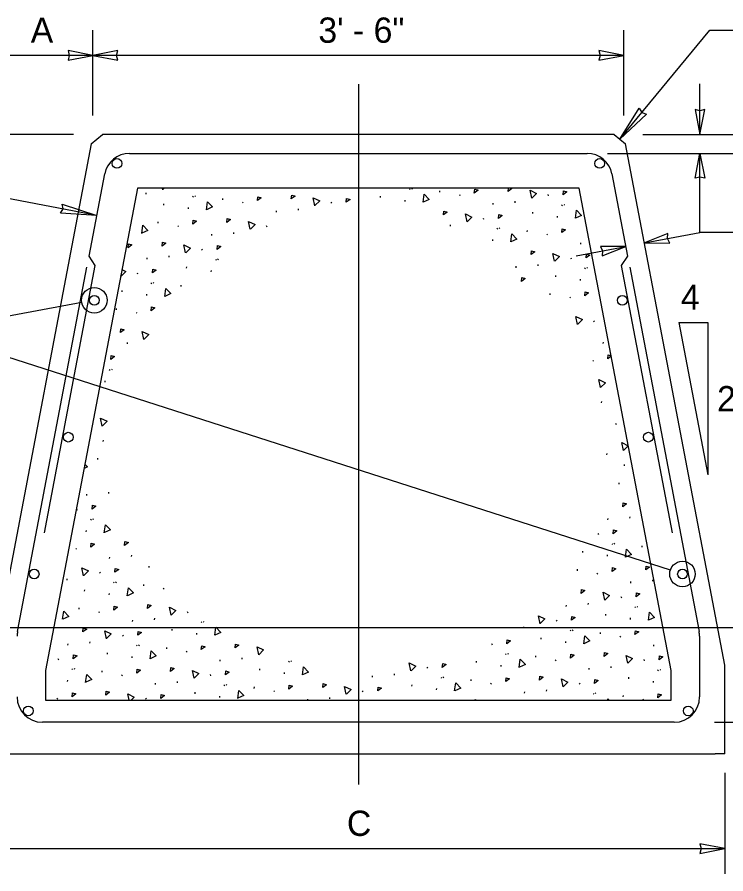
# Model space of a CAD drawing. Extents: x 99862 to 103151, y 100000 to 102076.
# Drawn here: x 100955 to 101404, y 100434 to 100977 of the extents above; entities that cross this region are included whole.
import ezdxf

# ---------------------------------------------------------------- set-up
doc = ezdxf.new("R2010")
doc.units = 0
for name, color, linetype in [('Level 10', 7, 'Continuous'), ('Level 13', 7, 'Continuous'), ('Level 15', 7, 'Continuous'), ('Level 2', 7, 'Continuous'), ('Level 20', 7, 'Continuous'), ('Level 8', 7, 'Continuous')]:
    doc.layers.add(name, color=color, linetype=linetype)

msp = doc.modelspace()

# ---------------------------------------------------------------- linework, layer by layer
at = {"layer": 'Level 10'}
for p, q in [((101026.08, 100890.26), (101315.75, 100890.26)), ((101000.45, 100825.21), (101010.36, 100877.26)), ((101331.47, 100877.26), (101341.38, 100825.21)), ((101004.42, 100819.36), (101000.45, 100825.21)), ((101341.38, 100825.21), (101337.41, 100819.36)), ((100955.2, 100587.61), (100999.13, 100818.26)), ((100972.18, 100650.08), (101004.42, 100819.36)), ((101337.41, 100819.36), (101369.65, 100650.08)), ((101342.71, 100818.26), (101386.64, 100587.63)), ((101386.92, 100584.64), (101386.92, 100546.26)), ((101370.92, 100530.26), (100970.91, 100530.26))]:
    msp.add_line(p, q, dxfattribs=at)
for centre in [(101018.1, 100883.91), (101323.73, 100883.91), (101003.79, 100797.29), (101338.05, 100797.29), (100987.29, 100710.67), (101354.55, 100710.67), (100965.7, 100624.05), (101376.13, 100624.05), (100962.07, 100537.43), (101379.76, 100537.43)]:
    msp.add_circle(centre, 3.08, dxfattribs=at)
for centre, start, end in [((101026.08, 100874.26), 90, 169.216), ((101315.75, 100874.26), 10.784, 90), ((100970.91, 100584.62), 169.2152, 180), ((101370.92, 100584.64), 360, 10.784), ((100970.91, 100546.26), 180, 270), ((101370.92, 100546.26), 270, 360)]:
    msp.add_arc(centre, 16, start, end, dxfattribs=at)
at = {"layer": 'Level 13'}
for p, q in [((101031.05, 100868.26), (100972.91, 100563.05)), ((101310.79, 100868.26), (101031.05, 100868.26)), ((101036.59, 100864.44), (101036.65, 100865.31)), ((101159.93, 100868), (101159.94, 100868.26)), ((101203.25, 100867.87), (101203.77, 100867.49)), ((101204.6, 100868.14), (101205.11, 100867.76)), ((101222.42, 100865.66), (101222.48, 100866.54)), ((101234.79, 100864.12), (101235.31, 100863.74)), ((101290.81, 100864.18), (101291.17, 100863.46)), ((101368.92, 100563.07), (101310.79, 100868.26)), ((101047.71, 100857.52), (101047.77, 100858.4)), ((101065.99, 100863.11), (101066.51, 100862.74)), ((101067.33, 100863.39), (101067.85, 100863.01)), ((101085.15, 100860.91), (101085.21, 100861.78)), ((101097.53, 100859.37), (101098.04, 100858.99)), ((101153.55, 100859.43), (101153.9, 100858.71)), ((101184.97, 100862.28), (101185.03, 100863.15)), ((101200.58, 100859.89), (101200.64, 100860.76)), ((101256.28, 100857.86), (101256.34, 100858.73)), ((101270.21, 100859.05), (101270.27, 100859.93)), ((101063.32, 100855.14), (101063.38, 100856.01)), ((101119.01, 100853.11), (101119.07, 100853.98)), ((101132.94, 100854.3), (101133, 100855.17)), ((101281.32, 100852.14), (101281.39, 100853.01)), ((101299.61, 100857.73), (101300.12, 100857.35)), ((101300.95, 100858), (101301.47, 100857.62)), ((101249.9, 100849.29), (101250.26, 100848.57)), ((101296.94, 100849.75), (101297, 100850.62)), ((101044.24, 100846.02), (101044.3, 100846.89)), ((101056.61, 100844.48), (101057.13, 100844.1)), ((101112.63, 100844.54), (101112.99, 100843.82)), ((101229.3, 100844.16), (101229.36, 100845.04)), ((101258.7, 100842.84), (101259.21, 100842.46)), ((101260.04, 100843.11), (101260.56, 100842.73)), ((101078.1, 100838.22), (101078.16, 100839.09)), ((101092.03, 100839.41), (101092.09, 100840.28)), ((101277.86, 100840.63), (101277.92, 100841.51)), ((101290.23, 100839.09), (101290.75, 100838.71)), ((101256.02, 100834.86), (101256.08, 100835.73)), ((101311.72, 100832.83), (101311.78, 100833.7)), ((101071.72, 100829.65), (101072.08, 100828.93)), ((101037.19, 100823.33), (101037.25, 100824.2)), ((101051.12, 100824.52), (101051.18, 100825.39)), ((101080.52, 100823.2), (101081.04, 100822.82)), ((101081.86, 100823.47), (101082.38, 100823.09)), ((101305.34, 100824.26), (101305.7, 100823.54)), ((101062.24, 100817.6), (101062.3, 100818.48)), ((101077.85, 100815.22), (101077.91, 100816.09)), ((101270.81, 100817.94), (101270.87, 100818.81)), ((101284.74, 100819.13), (101284.8, 100820.01)), ((101314.14, 100817.81), (101314.65, 100817.43)), ((101315.48, 100818.08), (101316, 100817.7)), ((101030.81, 100814.75), (101031.17, 100814.03)), ((101295.85, 100812.22), (101295.91, 100813.09)), ((101311.47, 100809.83), (101311.53, 100810.7)), ((101039.61, 100808.3), (101040.12, 100807.93)), ((101040.95, 100808.58), (101041.47, 100808.2)), ((101058.77, 100806.1), (101058.83, 100806.97)), ((101021.32, 100802.71), (101021.38, 100803.59)), ((101036.93, 100800.33), (101037, 100801.2)), ((101292.39, 100800.71), (101292.45, 100801.59)), ((101304.76, 100799.17), (101305.28, 100798.79)), ((101017.86, 100791.21), (101017.92, 100792.08)), ((101030.23, 100789.67), (101030.75, 100789.29)), ((101319.87, 100784.34), (101320.23, 100783.62)), ((101024.74, 100769.71), (101024.8, 100770.58)), ((101325.99, 100769.91), (101326.06, 100770.78)), ((101319.29, 100759.25), (101319.81, 100758.87)), ((101013.23, 100753.49), (101013.74, 100753.11)), ((101014.57, 100753.77), (101015.08, 100753.39)), ((101010.55, 100745.52), (101010.61, 100746.39)), ((101324.91, 100732.38), (101324.97, 100733.25)), ((101333.82, 100719.33), (101334.34, 100718.95)), ((101009.47, 100707.98), (101009.53, 100708.86)), ((101006, 100696.48), (101006.06, 100697.35)), ((101328.33, 100699.38), (101328.39, 100700.25)), ((101339.44, 100692.46), (101339.5, 100693.33)), ((101335.98, 100680.96), (101336.04, 100681.83)), ((100998.95, 100673.79), (100999.02, 100674.66)), ((101012.88, 100674.98), (101012.94, 100675.85)), ((100992.57, 100665.21), (100992.93, 100664.49)), ((101001.37, 100658.76), (101001.89, 100658.39)), ((101002.72, 100659.04), (101003.23, 100658.66)), ((101328.93, 100658.26), (101328.99, 100659.13)), ((101342.86, 100659.46), (101342.92, 100660.33)), ((100998.7, 100650.79), (100998.76, 100651.66)), ((101322.55, 100649.69), (101322.9, 100648.97)), ((101331.34, 100643.24), (101331.86, 100642.86)), ((101332.69, 100643.51), (101333.2, 100643.13)), ((101350.51, 100641.04), (101350.57, 100641.91)), ((100992, 100640.13), (100992.51, 100639.75)), ((101313.06, 100637.65), (101313.12, 100638.52)), ((101328.67, 100635.26), (101328.73, 100636.14)), ((101013.48, 100633.87), (101013.54, 100634.74)), ((101027.41, 100635.06), (101027.47, 100635.93)), ((101007.1, 100625.3), (101007.46, 100624.57)), ((101038.53, 100628.15), (101038.59, 100629.02)), ((101309.59, 100626.15), (101309.65, 100627.02)), ((100986.5, 100620.17), (100986.56, 100621.04)), ((101321.97, 100624.6), (101322.48, 100624.22)), ((101357.39, 100619.54), (101357.45, 100620.41)), ((101015.9, 100618.84), (101016.42, 100618.47)), ((101017.24, 100619.12), (101017.76, 100618.74)), ((101035.06, 100616.64), (101035.12, 100617.51)), ((101047.44, 100615.1), (101047.95, 100614.72)), ((101343.46, 100618.34), (101343.52, 100619.21)), ((100997.62, 100613.25), (100997.68, 100614.13)), ((101013.23, 100610.87), (101013.29, 100611.74)), ((101337.08, 100609.77), (101337.43, 100609.05)), ((101302.54, 100603.45), (101302.6, 100604.32)), ((101316.47, 100604.65), (101316.53, 100605.52)), ((101347.22, 100603.59), (101347.73, 100603.22)), ((100994.15, 100601.75), (100994.21, 100602.62)), ((101006.53, 100600.21), (101007.04, 100599.83)), ((101062.55, 100600.27), (101062.9, 100599.55)), ((101327.59, 100597.73), (101327.65, 100598.6)), ((101345.87, 100603.32), (101346.39, 100602.94)), ((101028.01, 100593.95), (101028.07, 100594.82)), ((101041.94, 100595.14), (101042, 100596.01)), ((101071.34, 100593.82), (101071.86, 100593.44)), ((101072.69, 100594.09), (101073.2, 100593.71)), ((101296.16, 100594.88), (101296.52, 100594.16)), ((101343.2, 100595.34), (101343.26, 100596.22)), ((101053.06, 100588.23), (101053.12, 100589.1)), ((101275.56, 100589.76), (101275.62, 100590.63)), ((101304.96, 100588.43), (101305.48, 100588.05)), ((101306.3, 100588.7), (101306.82, 100588.32)), ((101021.63, 100585.38), (101021.99, 100584.66)), ((101068.67, 100585.84), (101068.73, 100586.71)), ((101286.68, 100582.84), (101286.74, 100583.71)), ((101324.12, 100586.23), (101324.18, 100587.1)), ((101336.5, 100584.68), (101337.01, 100584.3)), ((100987.1, 100579.06), (100987.16, 100579.93)), ((101001.03, 100580.25), (101001.09, 100581.12)), ((101030.43, 100578.93), (101030.95, 100578.55)), ((101031.77, 100579.2), (101032.29, 100578.82)), ((101049.59, 100576.72), (101049.65, 100577.59)), ((101255.25, 100579.99), (101255.61, 100579.27)), ((101302.29, 100580.45), (101302.35, 100581.33)), ((101357.99, 100578.42), (101358.05, 100579.29)), ((101012.15, 100573.33), (101012.21, 100574.21)), ((101027.76, 100570.95), (101027.82, 100571.82)), ((101061.97, 100575.18), (101062.48, 100574.8)), ((101097.38, 100570.11), (101097.44, 100570.98)), ((101264.05, 100573.54), (101264.57, 100573.16)), ((101265.39, 100573.81), (101265.91, 100573.43)), ((101283.21, 100571.34), (101283.27, 100572.21)), ((100980.72, 100570.48), (100981.08, 100569.76)), ((101083.46, 100568.92), (101083.52, 100569.79)), ((101126.78, 100568.79), (101127.3, 100568.41)), ((101128.13, 100569.06), (101128.64, 100568.68)), ((101245.77, 100567.95), (101245.83, 100568.82)), ((101261.38, 100565.56), (101261.44, 100566.43)), ((101295.59, 100569.79), (101296.1, 100569.41)), ((101331, 100564.73), (101331.06, 100565.6)), ((101351.61, 100569.85), (101351.96, 100569.13)), ((100972.91, 100563.05), (100972.91, 100544.26)), ((100989.52, 100564.03), (100990.04, 100563.66)), ((100990.86, 100564.31), (100991.38, 100563.93)), ((101008.68, 100561.83), (101008.74, 100562.7)), ((101021.06, 100560.29), (101021.57, 100559.91)), ((101077.07, 100560.35), (101077.43, 100559.63)), ((101108.5, 100563.2), (101108.56, 100564.07)), ((101124.11, 100560.81), (101124.17, 100561.68)), ((101193.74, 100559.97), (101193.8, 100560.85)), ((101214.34, 100565.1), (101214.7, 100564.38)), ((101317.07, 100563.53), (101317.13, 100564.4)), ((101360.4, 100563.4), (101360.92, 100563.02)), ((101361.75, 100563.67), (101362.26, 100563.3)), ((101368.92, 100544.26), (101368.92, 100563.07)), ((100986.85, 100556.06), (100986.91, 100556.93)), ((101042.54, 100554.03), (101042.6, 100554.9)), ((101056.47, 100555.22), (101056.53, 100556.09)), ((101179.81, 100558.78), (101179.87, 100559.65)), ((101223.14, 100558.65), (101223.65, 100558.27)), ((101224.48, 100558.92), (101225, 100558.54)), ((101242.3, 100556.44), (101242.36, 100557.32)), ((101254.67, 100554.9), (101255.19, 100554.52)), ((101310.69, 100554.96), (101311.05, 100554.24)), ((101342.12, 100557.81), (101342.18, 100558.68)), ((101357.73, 100555.42), (101357.79, 100556.3)), ((101085.87, 100553.9), (101086.39, 100553.52)), ((101087.22, 100554.17), (101087.73, 100553.79)), ((101105.03, 100551.69), (101105.09, 100552.56)), ((101117.41, 100550.15), (101117.92, 100549.77)), ((101173.43, 100550.21), (101173.79, 100549.49)), ((101204.85, 100553.06), (101204.91, 100553.93)), ((101220.47, 100550.67), (101220.53, 100551.54)), ((101276.16, 100548.64), (101276.22, 100549.51)), ((101290.09, 100549.84), (101290.15, 100550.71)), ((100972.91, 100544.26), (101368.92, 100544.26)), ((100980.14, 100545.4), (100980.66, 100545.02)), ((101036.16, 100545.46), (101036.52, 100544.74)), ((101067.59, 100548.31), (101067.65, 100549.18)), ((101083.2, 100545.92), (101083.26, 100546.79)), ((101138.92, 100544.26), (101138.96, 100544.76)), ((101152.83, 100545.08), (101152.89, 100545.96)), ((101319.49, 100548.51), (101320.01, 100548.13)), ((101320.83, 100548.78), (101321.35, 100548.4)), ((101338.65, 100546.31), (101338.71, 100547.18)), ((101351.03, 100544.76), (101351.54, 100544.38))]:
    msp.add_line(p, q, dxfattribs=at)
for points in [[(101047.06, 100867.27), (101046.84, 100868.26)], [(101048.06, 100868.26), (101047.12, 100867.33)], [(101128.48, 100861.42), (101128.72, 100863.87), (101130.85, 100863.23), (101128.48, 100861.42)], [(101211.97, 100859.31), (101212.67, 100864.39), (101215.85, 100861.1), (101212.05, 100859.34)], [(101244.34, 100865.14), (101244.58, 100867.59), (101246.71, 100866.94), (101244.34, 100865.14)], [(101265.75, 100866.17), (101265.95, 100868.26)], [(101267.17, 100868.26), (101268.11, 100867.98), (101265.75, 100866.17)], [(101280.67, 100861.89), (101279.6, 100866.9), (101283.71, 100864.9), (101280.74, 100861.94)], [(101300.55, 100864.05), (101300.79, 100866.5), (101302.91, 100865.86), (101300.55, 100864.05)], [(101074.71, 100854.56), (101075.41, 100859.63), (101078.59, 100856.35), (101074.79, 100854.59)], [(101107.08, 100860.39), (101107.32, 100862.84), (101109.44, 100862.19), (101107.08, 100860.39)], [(101143.41, 100857.13), (101142.33, 100862.14), (101146.45, 100860.15), (101143.48, 100857.19)], [(101163.28, 100859.3), (101163.52, 100861.75), (101165.65, 100861.1), (101163.28, 100859.3)], [(101224.83, 100851.28), (101225.08, 100853.73), (101227.2, 100853.09), (101224.83, 100851.28)], [(101308.32, 100849.17), (101309.03, 100854.25), (101312.21, 100850.96), (101308.41, 100849.2)], [(101066.17, 100845.49), (101066.41, 100847.95), (101068.53, 100847.3), (101066.17, 100845.49)], [(101087.57, 100846.53), (101087.81, 100848.98), (101089.93, 100848.34), (101087.57, 100846.53)], [(101239.76, 100847), (101238.69, 100852.01), (101242.8, 100850.01), (101239.83, 100847.05)], [(101259.64, 100849.16), (101259.88, 100851.61), (101262, 100850.96), (101259.64, 100849.16)], [(101033.79, 100839.67), (101034.5, 100844.74), (101037.68, 100841.46), (101033.88, 100839.7)], [(101102.5, 100842.24), (101101.42, 100847.25), (101105.53, 100845.25), (101102.57, 100842.3)], [(101299.78, 100840.11), (101300.03, 100842.56), (101302.15, 100841.92), (101299.78, 100840.11)], [(101267.41, 100834.28), (101268.12, 100839.36), (101271.3, 100836.07), (101267.5, 100834.31)], [(101025.25, 100830.6), (101025.5, 100833.06), (101027.62, 100832.41), (101025.25, 100830.6)], [(101046.66, 100831.64), (101046.9, 100834.09), (101049.02, 100833.45), (101046.66, 100831.64)], [(101061.59, 100827.35), (101060.51, 100832.36), (101064.62, 100830.36), (101061.65, 100827.41)], [(101081.46, 100829.51), (101081.7, 100831.97), (101083.82, 100831.32), (101081.46, 100829.51)], [(101280.28, 100826.25), (101280.52, 100828.7), (101282.64, 100828.06), (101280.28, 100826.25)], [(101295.2, 100821.97), (101294.13, 100826.98), (101298.24, 100824.98), (101295.27, 100822.02)], [(101315.08, 100824.13), (101315.32, 100826.58), (101317.44, 100825.94), (101315.08, 100824.13)], [(101021.22, 100816.68), (101023.71, 100815.47), (101020.74, 100812.52)], [(101040.55, 100814.62), (101040.79, 100817.07), (101042.91, 100816.43), (101040.55, 100814.62)], [(101020.67, 100812.46), (101020.54, 100813.09)], [(101274.16, 100809.24), (101274.41, 100811.69), (101276.53, 100811.04), (101274.16, 100809.24)], [(101048.32, 100799.75), (101049.03, 100804.82), (101052.21, 100801.54), (101048.41, 100799.78)], [(101314.31, 100800.19), (101314.56, 100802.64), (101316.68, 100802), (101314.31, 100800.19)], [(101039.78, 100790.68), (101040.02, 100793.14), (101042.15, 100792.49), (101039.78, 100790.68)], [(101309.73, 100782.05), (101308.66, 100787.06), (101312.77, 100785.06), (101309.8, 100782.1)], [(101020.27, 100776.83), (101020.52, 100779.28), (101022.64, 100778.64), (101020.27, 100776.83)], [(101035.2, 100772.54), (101034.13, 100777.55), (101038.24, 100775.55), (101035.27, 100772.6)], [(101014.16, 100759.81), (101014.41, 100762.26), (101016.53, 100761.62), (101014.16, 100759.81)], [(101328.84, 100760.27), (101329.08, 100762.72), (101331, 100762.14)], [(101331.04, 100761.95), (101328.84, 100760.27)], [(101324.26, 100742.13), (101323.19, 100747.14), (101327.3, 100745.14), (101324.33, 100742.18)], [(101008.82, 100717.73), (101007.75, 100722.74), (101011.86, 100720.74), (101008.89, 100717.79)], [(101338.79, 100702.21), (101337.72, 100707.22), (101341.83, 100705.22), (101338.86, 100702.26)], [(100997.79, 100693.63), (100999.44, 100691.92), (100997.27, 100690.91)], [(101338.39, 100666.58), (101338.64, 100669.03), (101340.76, 100668.38), (101338.39, 100666.58)], [(101002.31, 100665.08), (101002.55, 100667.53), (101004.68, 100666.89), (101002.31, 100665.08)], [(101010.09, 100650.21), (101010.79, 100655.28), (101013.97, 100652), (101010.17, 100650.24)], [(101332.28, 100649.56), (101332.52, 100652.01), (101334.65, 100651.37), (101332.28, 100649.56)], [(101001.55, 100641.14), (101001.79, 100643.6), (101003.91, 100642.95), (101001.55, 100641.14)], [(101022.95, 100642.18), (101023.19, 100644.63), (101025.32, 100643.99), (101022.95, 100642.18)], [(101340.06, 100634.68), (101340.76, 100639.76), (101343.94, 100636.47), (101340.14, 100634.71)], [(100996.97, 100623), (100995.89, 100628.01), (101000, 100626.01), (100997.04, 100623.06)], [(101016.84, 100625.16), (101017.08, 100627.62), (101019.21, 100626.97), (101016.84, 100625.16)], [(101331.52, 100625.62), (101331.76, 100628.07), (101333.89, 100627.43), (101331.52, 100625.62)], [(101352.92, 100626.66), (101353.16, 100629.11), (101355.29, 100628.46), (101352.92, 100626.66)], [(101024.62, 100610.29), (101025.32, 100615.36), (101028.5, 100612.08), (101024.7, 100610.32)], [(101312.01, 100611.77), (101312.25, 100614.22), (101314.38, 100613.57), (101312.01, 100611.77)], [(101326.94, 100607.48), (101325.87, 100612.49), (101329.98, 100610.49), (101327.01, 100607.53)], [(101346.81, 100609.64), (101347.05, 100612.09), (101349.18, 100611.45), (101346.81, 100609.64)], [(101016.08, 100601.23), (101016.32, 100603.68), (101018.44, 100603.03), (101016.08, 100601.23)], [(101037.48, 100602.26), (101037.72, 100604.71), (101039.85, 100604.07), (101037.48, 100602.26)], [(100983.71, 100595.4), (100984.41, 100600.47), (100987.59, 100597.19), (100983.79, 100595.43)], [(101052.41, 100597.97), (101051.33, 100602.98), (101055.45, 100600.98), (101052.48, 100598.03)], [(101354.59, 100594.76), (101355.29, 100599.84), (101358.47, 100596.56), (101354.67, 100594.79)], [(101286.03, 100592.59), (101284.95, 100597.6), (101289.06, 100595.6), (101286.1, 100592.64)], [(101305.9, 100594.75), (101306.14, 100597.2), (101308.27, 100596.56), (101305.9, 100594.75)], [(100996.57, 100587.37), (100996.81, 100589.82), (100998.94, 100589.18), (100996.57, 100587.37)], [(101011.5, 100583.08), (101010.42, 100588.09), (101014.53, 100586.09), (101011.57, 100583.14)], [(101031.37, 100585.25), (101031.61, 100587.7), (101033.74, 100587.05), (101031.37, 100585.25)], [(101080.06, 100585.26), (101080.76, 100590.33), (101083.94, 100587.05), (101080.14, 100585.29)], [(101346.05, 100585.7), (101346.29, 100588.15), (101348.42, 100587.51), (101346.05, 100585.7)], [(101264.99, 100579.86), (101265.23, 100582.31), (101267.35, 100581.67), (101264.99, 100579.86)], [(101313.68, 100579.87), (101314.38, 100584.95), (101317.56, 100581.66), (101313.76, 100579.9)], [(101071.52, 100576.2), (101071.76, 100578.65), (101073.89, 100578), (101071.52, 100576.2)], [(101092.92, 100577.23), (101093.16, 100579.68), (101095.29, 100579.04), (101092.92, 100577.23)], [(101107.85, 100572.94), (101106.78, 100577.95), (101110.89, 100575.96), (101107.92, 100573)], [(100990.46, 100570.35), (100990.7, 100572.81), (100992.82, 100572.16), (100990.46, 100570.35)], [(101039.15, 100570.37), (101039.85, 100575.44), (101043.03, 100572.16), (101039.23, 100570.4)], [(101305.14, 100570.81), (101305.38, 100573.26), (101307.5, 100572.62), (101305.14, 100570.81)], [(101326.54, 100571.85), (101326.78, 100574.3), (101328.91, 100573.65), (101326.54, 100571.85)], [(101341.47, 100567.56), (101340.39, 100572.57), (101344.51, 100570.57), (101341.54, 100567.62)], [(101361.34, 100569.72), (101361.58, 100572.17), (101363.71, 100571.53), (101361.34, 100569.72)], [(101204.2, 100562.81), (101203.13, 100567.82), (101207.24, 100565.82), (101204.27, 100562.86)], [(101224.08, 100564.97), (101224.32, 100567.42), (101226.44, 100566.78), (101224.08, 100564.97)], [(101272.77, 100564.98), (101273.47, 100570.06), (101276.65, 100566.77), (101272.85, 100565.01)], [(100998.24, 100555.48), (100998.94, 100560.55), (101002.12, 100557.27), (100998.32, 100555.51)], [(101030.61, 100561.31), (101030.85, 100563.76), (101032.97, 100563.11), (101030.61, 100561.31)], [(101052.01, 100562.34), (101052.25, 100564.79), (101054.38, 100564.15), (101052.01, 100562.34)], [(101066.94, 100558.05), (101065.86, 100563.06), (101069.98, 100561.07), (101067.01, 100558.11)], [(101086.81, 100560.22), (101087.05, 100562.67), (101089.18, 100562.02), (101086.81, 100560.22)], [(101135.5, 100560.23), (101136.2, 100565.31), (101139.38, 100562.02), (101135.58, 100560.26)], [(101231.85, 100550.09), (101232.56, 100555.17), (101235.74, 100551.88), (101231.94, 100550.12)], [(101264.23, 100555.92), (101264.47, 100558.37), (101266.59, 100557.73), (101264.23, 100555.92)], [(101285.63, 100556.95), (101285.87, 100559.41), (101287.99, 100558.76), (101285.63, 100556.95)], [(101300.56, 100552.67), (101299.48, 100557.68), (101303.59, 100555.68), (101300.63, 100552.72)], [(101320.43, 100554.83), (101320.67, 100557.28), (101322.8, 100556.64), (101320.43, 100554.83)], [(101011.1, 100547.45), (101011.34, 100549.9), (101013.46, 100549.26), (101011.1, 100547.45)], [(101094.59, 100545.34), (101095.29, 100550.41), (101098.47, 100547.13), (101094.67, 100545.37)], [(101126.96, 100551.17), (101127.2, 100553.62), (101129.33, 100552.97), (101126.96, 100551.17)], [(101148.36, 100552.2), (101148.61, 100554.65), (101150.73, 100554.01), (101148.36, 100552.2)], [(101163.29, 100547.92), (101162.22, 100552.93), (101166.33, 100550.93), (101163.36, 100547.97)], [(101183.16, 100550.08), (101183.41, 100552.53), (101185.53, 100551.88), (101183.16, 100550.08)], [(100989.69, 100546.41), (100989.94, 100548.87), (100992.06, 100548.22), (100989.69, 100546.41)], [(101025.79, 100544.26), (101024.95, 100548.17), (101029.06, 100546.17), (101027.14, 100544.26)], [(101045.9, 100545.33), (101046.14, 100547.78), (101048.27, 100547.13), (101045.9, 100545.33)], [(101244.93, 100544.26), (101244.96, 100544.52), (101245.78, 100544.26)], [(101328.81, 100544.26), (101328.91, 100545.03), (101329.65, 100544.26)], [(101360.58, 100545.78), (101360.82, 100548.23), (101362.94, 100547.59), (101360.58, 100545.78)]]:
    msp.add_lwpolyline(points, dxfattribs=at)
at = {"layer": 'Level 15'}
for p, q in [((101002.92, 100914.26), (101002.92, 100968.26)), ((101336.49, 100899.32), (101393.37, 100968.26)), ((101338.92, 100914.26), (101338.92, 100968.26)), ((101393.37, 100968.26), (101409.37, 100968.26)), ((101002.92, 100952.26), (100938.92, 100952.26)), ((101338.92, 100952.26), (101002.92, 100952.26)), ((101387.17, 100902.26), (101387.17, 100934.26)), ((101170.92, 100934.11), (101170.92, 100490.76)), ((100990.7, 100902.26), (100765.96, 100902.26)), ((101351.13, 100902.26), (101664.92, 100902.26)), ((101328.71, 100890.26), (101614.92, 100890.26)), ((101387.17, 100840.26), (101387.17, 100890.26)), ((101005.36, 100851.02), (100897.76, 100871.52)), ((101352.01, 100833.57), (101387.17, 100840.26)), ((101459.6, 100840.26), (101387.17, 100840.26)), ((101308.79, 100825.34), (101340.22, 100831.32)), ((100995.84, 100795.82), (100897.76, 100777.71)), ((101373.74, 100783.26), (101392.13, 100783.26)), ((101373.74, 100783.26), (101392.13, 100686.73)), ((101392.13, 100783.26), (101392.13, 100686.73)), ((101368.44, 100626.52), (100897.76, 100777.71)), ((101396.38, 100530.26), (101614.92, 100530.26)), ((101402.92, 100498.27), (101402.92, 100434.26)), ((100938.91, 100450.26), (101402.92, 100450.26))]:
    msp.add_line(p, q, dxfattribs=at)
for points in [[(101002.91, 100952.26), (100987.19, 100955.35), (100987.92, 100952.26), (100987.19, 100949.18)], [(101002.91, 100952.26), (101018.64, 100949.18), (101017.91, 100952.26), (101018.64, 100955.35)], [(101338.91, 100952.26), (101323.19, 100955.35), (101323.92, 100952.26), (101323.19, 100949.18)], [(101336.48, 100899.32), (101348.71, 100918.83), (101350.34, 100916.11), (101353.32, 100915.03)], [(101387.16, 100902.26), (101390.25, 100917.99), (101387.16, 100917.26), (101384.08, 100917.99)], [(101387.16, 100890.26), (101390.25, 100874.54), (101387.16, 100875.27), (101384.08, 100874.54)], [(101005.36, 100851.02), (100982.38, 100852.36), (100983.97, 100855.09), (100983.49, 100858.23)], [(101352.01, 100833.57), (101368.03, 100833.48), (101366.74, 100836.38), (101366.88, 100839.54)], [(101340.22, 100831.32), (101324.19, 100831.41), (101325.49, 100828.52), (101325.35, 100825.35)], [(101402.92, 100450.26), (101387.19, 100453.35), (101387.92, 100450.26), (101387.19, 100447.18)]]:
    msp.add_lwpolyline(points, close=True, dxfattribs=at)
for centre in [(101003.79, 100797.29), (101376.13, 100624.05)]:
    msp.add_circle(centre, 8.08, dxfattribs=at)
at = {"layer": 'Level 2'}
for p, q in [((101005.35, 100899.32), (101008.91, 100902.26)), ((101332.92, 100902.26), (101008.91, 100902.26)), ((101332.92, 100902.26), (101336.49, 100899.32)), ((101001.79, 100896.37), (100938.91, 100566.26)), ((101001.79, 100896.37), (101005.35, 100899.32)), ((101336.49, 100899.32), (101340.05, 100896.37)), ((101402.92, 100566.28), (101340.05, 100896.37)), ((101402.92, 100510.26), (101402.92, 100566.28)), ((100944.91, 100510.26), (101396.92, 100510.26)), ((101402.92, 100510.26), (101396.92, 100510.26))]:
    msp.add_line(p, q, dxfattribs=at)
at = {"layer": 'Level 8'}
msp.add_line((100715.96, 100590.26), (101509.12, 100590.26), dxfattribs=at)

# ---------------------------------------------------------------- texts
at = {"layer": 'Level 20'}
for s, p in [('A', (100963.52, 100960.28)), ('3\' - 6"', (101145.59, 100960.28)), ('4', (101375.14, 100791.27)), ('21', (101398.02, 100727.01)), ('C', (101163.68, 100458.28))]:
    msp.add_text(s, height=16, dxfattribs=at).set_placement(p)

doc.saveas('drawing.dxf')
